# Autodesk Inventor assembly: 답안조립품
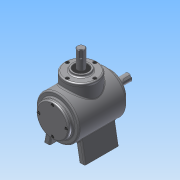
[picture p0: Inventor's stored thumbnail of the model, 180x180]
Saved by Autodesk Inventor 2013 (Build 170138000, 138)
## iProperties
Created: 2015-01
Part Number: 답안조립품
Document SubType Name: Assembly
Designer: Administrator
Author: Administrator
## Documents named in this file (15)
- C:\Users\Administrator\Desktop\450106V1029김아랑\답안조립품.iam
- C:\Users\Administrator\Desktop\450106V1029김아랑\답안본체.ipt
- C:\Users\Administrator\Desktop\450106V1029김아랑\M4.ipt
- C:\Users\Administrator\Desktop\450106V1029김아랑\메인 베벨기어.ipt
- C:\Users\Administrator\Desktop\450106V1029김아랑\메인 축.ipt
- 메인 축.ipt
- C:\Users\Administrator\Desktop\450106V1029김아랑\베어링 6203.ipt
- C:\Users\Administrator\Desktop\450106V1029김아랑\서브 베벨기어.ipt
- C:\Users\Administrator\Desktop\450106V1029김아랑\서브 축.ipt
- 서브 축.ipt
- C:\Users\Administrator\Desktop\450106V1029김아랑\오일실.ipt
- C:\Users\Administrator\Desktop\450106V1029김아랑\커버.ipt
- C:\Users\Administrator\Desktop\450106V1029김아랑\커버2.ipt
- C:\Users\Administrator\Desktop\450106V1029김아랑\키 4x4.ipt
- C:\Users\Administrator\Desktop\450106V1029김아랑\키 5x5.ipt
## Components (12 placed, 1 different names)
1. M4:3
2. M4:2
3. M4:4
4. M4:5
5. M4:6
6. M4:7
7. M4:8
8. M4:9
9. M4:1
10. M4:10
11. M4:11
12. M4:12
